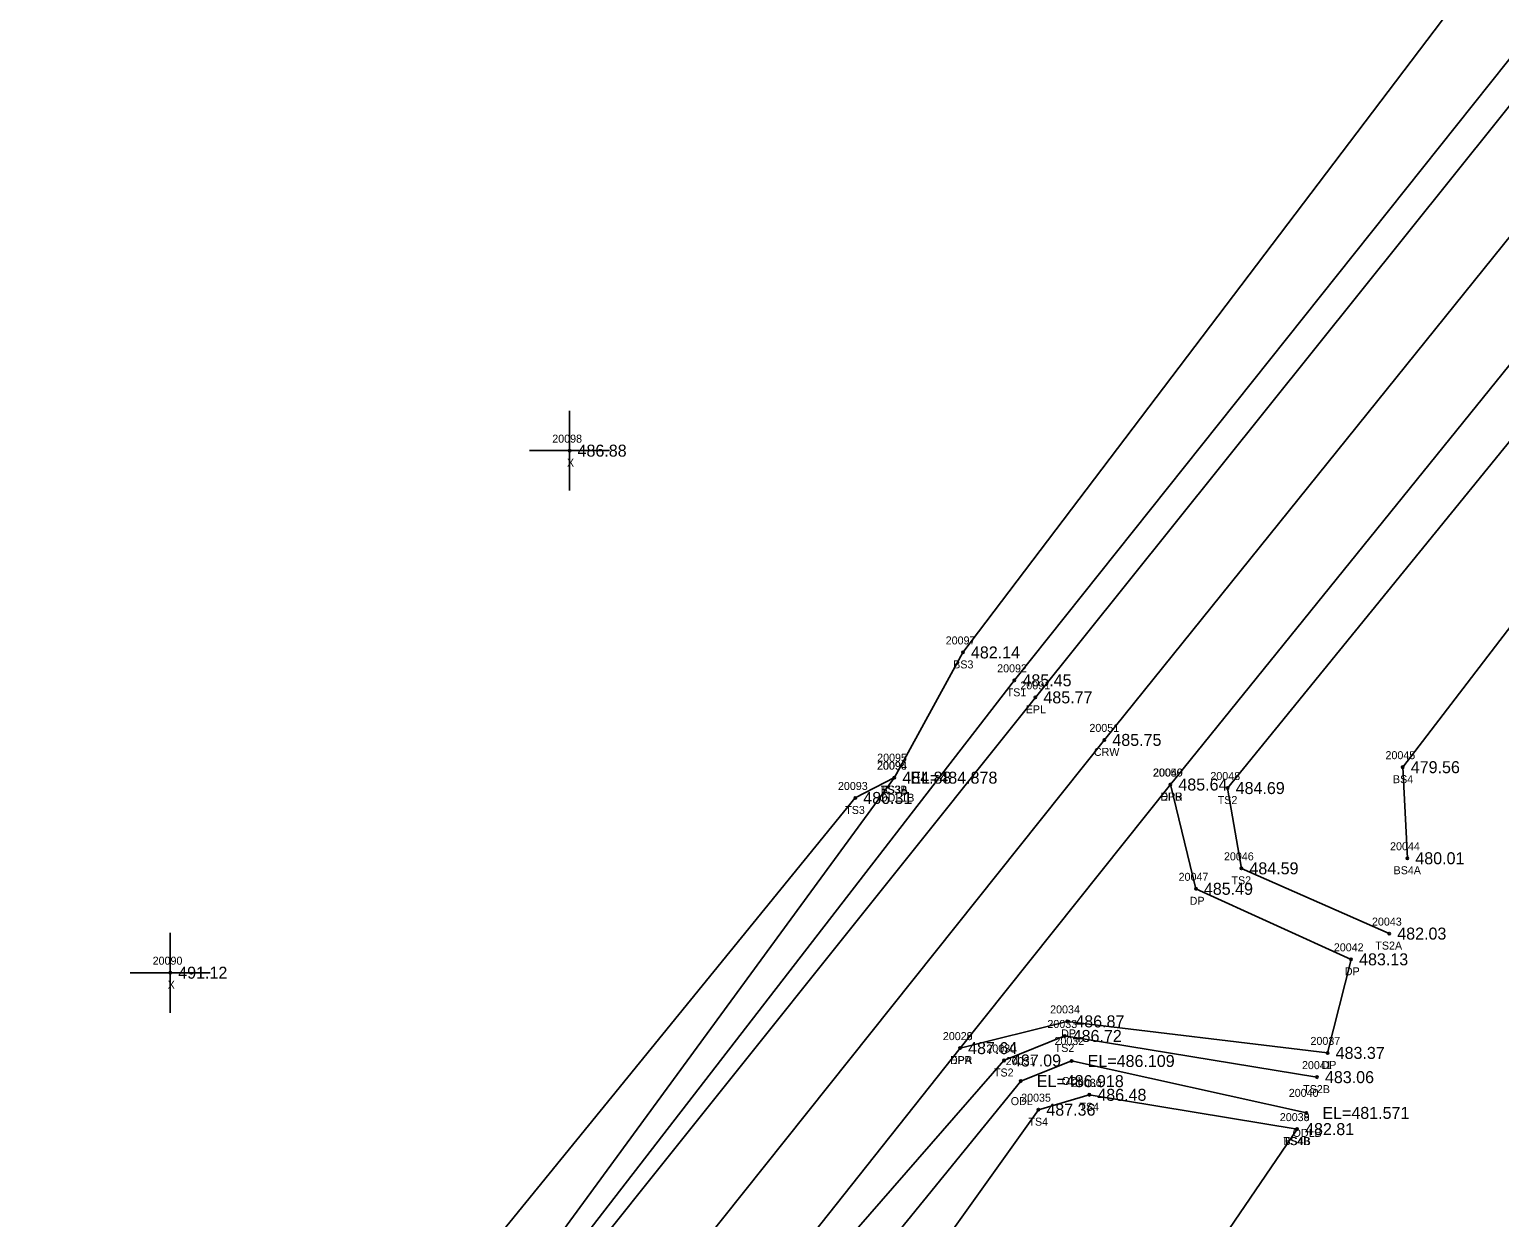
# Model space of a CAD drawing. Extents: x 1789565 to 1790548, y 909019 to 910194.
# Drawn here: x 1789730.3 to 1789914, y 909307.2 to 909455.8 of the extents above; entities that cross this region are included whole.
import ezdxf

# ---------------------------------------------------------------- set-up
doc = ezdxf.new("R2010")
doc.units = 0
for name, color, linetype in [('RD_DTM_BkLn1', 7, 'Continuous'), ('RD_DTM_BkLn2', 7, 'Continuous'), ('RD_DTM_BkLn_txCode', 7, 'Continuous'), ('RD_EX_Driveway', 7, 'Continuous'), ('RD_EX_Driveway_txCode', 7, 'Continuous'), ('RD_EX_H2O', 7, 'Continuous'), ('RD_EX_H2O_txCode', 7, 'Continuous'), ('RD_EX_Misc', 7, 'Continuous'), ('RD_EX_Misc_txCode', 7, 'Continuous'), ('RD_EX_Road', 7, 'Continuous'), ('RD_EX_Road_txCode', 7, 'Continuous'), ('RD_EX_TX_Driveway_ELEV', 7, 'Continuous'), ('RD_EX_TX_H2O_ELEV', 7, 'Continuous'), ('RD_EX_TX_Misc_ELEV', 7, 'Continuous'), ('RD_EX_TX_Road_ELEV', 7, 'Continuous'), ('RD_HC_Survey_ELEV', 7, 'Continuous'), ('RD_HC_Survey_txCode', 7, 'Continuous'), ('RD_SMD_Locator', 7, 'Continuous')]:
    doc.layers.add(name, color=color, linetype=linetype)

msp = doc.modelspace()

# ---------------------------------------------------------------- linework, layer by layer
at = {"layer": 'RD_DTM_BkLn1'}
msp.add_lwpolyline([(1789624.5, 909066.24), (1789686.15, 909143.09), (1789745.11, 909217.37), (1789803.6, 909290.4), (1789864.63, 909366.97), (1789927.82, 909445.41), (1789987.57, 909520.69), (1790044.94, 909592.68)], dxfattribs=at)
at = {"layer": 'RD_DTM_BkLn2'}
for points in [[(1789838.38, 909362.25), (1789846.95, 909377.91), (1789909.75, 909460.83), (1789970.57, 909536.24), (1790016.56, 909597.04), (1790029.06, 909609.68), (1790034.63, 909603.55)], [(1789902.5, 909352.17), (1789901.93, 909363.56), (1789951.8, 909428.72), (1790013.3, 909502.93), (1790049.48, 909550.91), (1790055.89, 909557.37), (1790063.97, 909580.51), (1790058.82, 909587.37), (1790034.63, 909603.55)], [(1789614.08, 909073.14), (1789676.68, 909150.35), (1789735.2, 909226.02), (1789793.81, 909297.32), (1789853.39, 909374.42), (1789917.15, 909454.46), (1789977.25, 909529.33), (1790025.37, 909589.9), (1790030.46, 909600.52), (1790034.43, 909600.71)], [(1789900.24, 909342.75), (1789881.76, 909350.91), (1789880.04, 909360.95), (1789940.57, 909435.39), (1790001.5, 909510.33), (1790055.89, 909575.68), (1790057.84, 909580.4), (1790055.44, 909584.35)], [(1789609.37, 909078.57), (1789669.9, 909156.07), (1789730.1, 909230.49), (1789787.39, 909303.09), (1789833.49, 909359.71), (1789838.38, 909362.25)], [(1789633.72, 909058.98), (1789695.06, 909135.14), (1789755.1, 909209.21), (1789813.73, 909282.9), (1789852.08, 909326.88), (1789859.67, 909329.95), (1789891.2, 909324.8)], [(1789638.21, 909054.4), (1789699.85, 909129.71), (1789733.31, 909172.18), (1789761.89, 909201.9), (1789823.56, 909274.73), (1789856.38, 909320.73), (1789862.75, 909322.59), (1789888.72, 909318.3)], [(1789733.31, 909172.18), (1789769.9, 909194.21), (1789846.28, 909255.95), (1789888.72, 909318.3)]]:
    msp.add_lwpolyline(points, dxfattribs=at)
at = {"layer": 'RD_EX_Driveway'}
msp.add_lwpolyline([(1789846.6, 909328.43), (1789860, 909331.77), (1789892.54, 909327.83), (1789895.47, 909339.53), (1789876.07, 909348.35), (1789872.88, 909361.39)], dxfattribs=at)
at = {"layer": 'RD_EX_H2O'}
for points in [[(1789612.38, 909074.81), (1789674.47, 909151.77), (1789733.61, 909227.27), (1789792.01, 909298.88), (1789838.38, 909362.25)], [(1789635.36, 909056.96), (1789697.2, 909133.38), (1789758.1, 909206.33), (1789818.22, 909280.06), (1789854.18, 909324.3), (1789860.54, 909326.82), (1789889.88, 909320.33)]]:
    msp.add_lwpolyline(points, dxfattribs=at)
at = {"layer": 'RD_EX_Misc'}
for p, q in [((1789797.78, 909398.14), (1789797.78, 909408.14)), ((1789792.78, 909403.14), (1789802.78, 909403.14)), ((1789747.87, 909332.86), (1789747.87, 909342.86)), ((1789742.87, 909337.86), (1789752.87, 909337.86))]:
    msp.add_line(p, q, dxfattribs=at)
at = {"layer": 'RD_EX_Road'}
for points in [[(1789616.04, 909073.03), (1789678, 909149.36), (1789737.65, 909223.89), (1789795.32, 909296.33), (1789856.01, 909372.29), (1789919.82, 909451.94), (1789979.86, 909527.13), (1790037.32, 909598.58), (1790044.94, 909592.68)], [(1789632.25, 909060.17), (1789693.63, 909136.51), (1789752.94, 909210.84), (1789811.79, 909284.47), (1789846.6, 909328.43), (1789872.88, 909361.39), (1789936.05, 909439.58), (1789995.85, 909514.58), (1790052.72, 909586.51), (1790044.94, 909592.68)]]:
    msp.add_lwpolyline(points, dxfattribs=at)
at = {"layer": 'RD_SMD_Locator'}
for centre in [(1789797.78, 909403.14), (1789846.95, 909377.91), (1789853.39, 909374.42), (1789856.01, 909372.29), (1789864.63, 909366.97), (1789901.93, 909363.56), (1789838.38, 909362.25), (1789838.38, 909362.25), (1789838.38, 909362.25), (1789872.88, 909361.39), (1789872.88, 909361.39), (1789880.04, 909360.95), (1789833.49, 909359.71), (1789881.76, 909350.91), (1789902.5, 909352.17), (1789876.07, 909348.35), (1789900.24, 909342.75), (1789895.47, 909339.53), (1789747.87, 909337.86), (1789860, 909331.77), (1789859.67, 909329.95), (1789846.6, 909328.43), (1789846.6, 909328.43), (1789852.08, 909326.88), (1789860.54, 909326.82), (1789892.54, 909327.83), (1789891.2, 909324.8), (1789854.18, 909324.3), (1789862.75, 909322.59), (1789856.38, 909320.73), (1789889.88, 909320.33), (1789888.72, 909318.3), (1789888.72, 909318.3)]:
    msp.add_circle(centre, 0.15, dxfattribs=at)

# ---------------------------------------------------------------- texts
at = {"layer": 'RD_DTM_BkLn_txCode'}
for s, p in [('20097', (1789844.8, 909378.91)), ('BS3', (1789845.73, 909375.91)), ('20092', (1789851.23, 909375.42)), ('TS1', (1789852.42, 909372.42)), ('20045', (1789899.77, 909364.56)), ('20096', (1789836.2, 909363.25)), ('20094', (1789836.23, 909363.25)), ('20093', (1789831.33, 909360.71)), ('20048', (1789877.88, 909361.95)), ('BS4', (1789900.7, 909361.56)), ('TS3B', (1789836.67, 909360.25)), ('BS3A', (1789836.67, 909360.25)), ('TS2', (1789878.8, 909358.95)), ('TS3', (1789832.24, 909357.71)), ('20046', (1789879.58, 909351.91)), ('20044', (1789900.34, 909353.17)), ('BS4A', (1789900.78, 909350.17)), ('TS2', (1789880.52, 909348.91)), ('20043', (1789898.08, 909343.75)), ('TS2A', (1789898.5, 909340.75)), ('20033', (1789857.51, 909330.95)), ('20030', (1789849.88, 909327.88)), ('TS2', (1789858.42, 909327.95)), ('20041', (1789889.33, 909325.8)), ('TS2', (1789850.83, 909324.88)), ('20036', (1789860.57, 909323.59)), ('TS2B', (1789889.48, 909322.8)), ('20035', (1789854.23, 909321.73)), ('TS4', (1789861.51, 909320.59)), ('TS4', (1789855.14, 909318.73)), ('20038', (1789886.56, 909319.3)), ('20039', (1789886.56, 909319.3)), ('TS4B', (1789887, 909316.3)), ('BS4B', (1789887.01, 909316.3))]:
    msp.add_text(s, height=1, dxfattribs=at).set_placement(p)
at = {"layer": 'RD_EX_Driveway_txCode'}
for s, p in [('20049', (1789870.73, 909362.39)), ('DPB', (1789871.63, 909359.39)), ('20047', (1789873.91, 909349.35)), ('DP', (1789875.29, 909346.35)), ('20042', (1789893.31, 909340.53)), ('DP', (1789894.69, 909337.53)), ('20034', (1789857.85, 909332.77)), ('DP', (1789859.22, 909329.77)), ('20029', (1789844.44, 909329.43)), ('20037', (1789890.39, 909328.83)), ('DPA', (1789845.33, 909326.43)), ('DP', (1789891.77, 909325.83))]:
    msp.add_text(s, height=1, dxfattribs=at).set_placement(p)
at = {"layer": 'RD_EX_H2O_txCode'}
for s, p in [('20095', (1789836.23, 909364.25)), ('ODL1B', (1789836.5, 909359.25)), ('20032', (1789858.39, 909328.82)), ('20031', (1789852.3, 909326.3)), ('ODL', (1789859.3, 909323.82)), ('20040', (1789887.68, 909322.33)), ('ODL', (1789852.93, 909321.3)), ('ODLB', (1789888.16, 909317.33))]:
    msp.add_text(s, height=1, dxfattribs=at).set_placement(p)
at = {"layer": 'RD_EX_Misc_txCode'}
for s, p in [('20098', (1789795.62, 909404.14)), ('X', (1789797.46, 909401.14)), ('20090', (1789745.67, 909338.86)), ('X', (1789747.55, 909335.86))]:
    msp.add_text(s, height=1, dxfattribs=at).set_placement(p)
at = {"layer": 'RD_EX_Road_txCode'}
for s, p in [('20091', (1789854.13, 909373.29)), ('EPL', (1789854.8, 909370.29)), ('20050', (1789870.69, 909362.39)), ('EPR', (1789871.65, 909359.39)), ('20028', (1789844.44, 909329.43)), ('EPR', (1789845.37, 909326.43))]:
    msp.add_text(s, height=1, dxfattribs=at).set_placement(p)
at = {"layer": 'RD_EX_TX_Driveway_ELEV'}
for s, p in [('485.64', (1789873.88, 909360.64)), ('485.49', (1789877.07, 909347.6)), ('483.13', (1789896.47, 909338.78)), ('486.87', (1789861, 909331.02)), ('487.64', (1789847.6, 909327.68)), ('483.37', (1789893.54, 909327.08))]:
    msp.add_text(s, height=1.5, dxfattribs=at).set_placement(p)
at = {"layer": 'RD_EX_TX_H2O_ELEV'}
for s, p in [('EL=484.878', (1789840.38, 909361.5)), ('EL=486.109', (1789862.54, 909326.07)), ('EL=486.918', (1789856.18, 909323.55)), ('EL=481.571', (1789891.88, 909319.58))]:
    msp.add_text(s, height=1.5, dxfattribs=at).set_placement(p)
at = {"layer": 'RD_EX_TX_Misc_ELEV'}
for s, p in [('486.88', (1789798.78, 909402.39)), ('482.14', (1789847.95, 909377.16)), ('485.45', (1789854.39, 909373.67)), ('479.56', (1789902.93, 909362.81)), ('484.88', (1789839.38, 909361.5)), ('484.88', (1789839.38, 909361.5)), ('484.69', (1789881.04, 909360.2)), ('486.31', (1789834.49, 909358.96)), ('480.01', (1789903.5, 909351.42)), ('484.59', (1789882.76, 909350.16)), ('482.03', (1789901.24, 909342)), ('491.12', (1789748.87, 909337.11)), ('486.72', (1789860.67, 909329.2)), ('487.09', (1789853.08, 909326.13)), ('483.06', (1789892.2, 909324.05)), ('486.48', (1789863.75, 909321.84)), ('487.36', (1789857.38, 909319.98)), ('482.81', (1789889.72, 909317.55)), ('482.81', (1789889.72, 909317.55))]:
    msp.add_text(s, height=1.5, dxfattribs=at).set_placement(p)
at = {"layer": 'RD_EX_TX_Road_ELEV'}
for s, p in [('485.77', (1789857.01, 909371.54)), ('485.64', (1789873.88, 909360.64)), ('487.64', (1789847.6, 909327.68))]:
    msp.add_text(s, height=1.5, dxfattribs=at).set_placement(p)
at = {"layer": 'RD_HC_Survey_ELEV'}
msp.add_text('485.75', height=1.5, dxfattribs=at).set_placement((1789865.63, 909366.22))
at = {"layer": 'RD_HC_Survey_txCode'}
for s, p in [('20051', (1789862.76, 909367.97)), ('CRW', (1789863.32, 909364.97))]:
    msp.add_text(s, height=1, dxfattribs=at).set_placement(p)

doc.saveas('drawing.dxf')
